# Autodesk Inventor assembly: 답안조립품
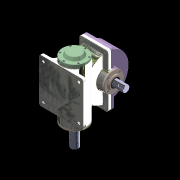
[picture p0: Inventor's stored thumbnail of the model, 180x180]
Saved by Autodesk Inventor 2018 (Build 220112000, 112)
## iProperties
Created: 2023-07
Part Number: 답안조립품
Material: 일반
Document SubType Name: Assembly
Designer: home
Author: home
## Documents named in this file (14)
- C:\Users\kimgi\Desktop\730706V1014\답안조립품.iam
- C:\Users\kimgi\Desktop\730706V1014\본체.ipt
- C:\Users\kimgi\Desktop\730706V1014\뒤커버.ipt
- C:\Users\kimgi\Desktop\730706V1014\앞커버.ipt
- C:\Users\kimgi\Desktop\730706V1014\깊은 홈 볼 베어링 6209.ipt
- C:\Users\kimgi\Desktop\730706V1014\웜 샤프트.ipt
- C:\Users\kimgi\Desktop\730706V1014\오일 실 35 55 11.ipt
- C:\Users\kimgi\Desktop\730706V1014\서브커버.ipt
- C:\Users\kimgi\Desktop\730706V1014\깊은 홈 볼 베어링 6206.ipt
- C:\Users\kimgi\Desktop\730706V1014\오일 실 30 42 7.ipt
- C:\Users\kimgi\Desktop\730706V1014\웜 휠.ipt
- C:\Users\kimgi\Desktop\730706V1014\본체 커버.ipt
- C:\Users\kimgi\Desktop\730706V1014\육각 소켓 머리 볼트 M5 x 12.ipt
- C:\Users\kimgi\Desktop\730706V1014\육각 소켓 머리 볼트 M6 x 20.ipt
## Component patterns: 구성요소 패턴 4:2 (2 elements)
